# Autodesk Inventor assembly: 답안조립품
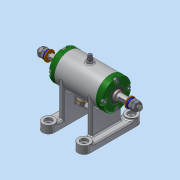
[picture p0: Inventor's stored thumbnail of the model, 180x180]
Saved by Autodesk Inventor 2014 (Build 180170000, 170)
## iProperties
Created: 2015-11
Part Number: 답안조립품
Document SubType Name: Assembly
Designer: 103-21
Author: 103-21
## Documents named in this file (16)
- C:\Users\103-21\Desktop\451110V1030\답안조립품.iam
- C:\Users\103-21\Desktop\451110V1030\1-본체.ipt
- C:\Users\103-21\Desktop\451110V1030\V벨트풀리.ipt
- C:\Users\103-21\Desktop\451110V1030\너트 M 8.ipt
- C:\Users\103-21\Desktop\451110V1030\니플 M 6 x 0.75.ipt
- C:\Users\103-21\Desktop\451110V1030\베어링 15 x 32 x 9.ipt
- C:\Users\103-21\Desktop\451110V1030\볼트 M 6 x 8.ipt
- C:\Users\103-21\Desktop\451110V1030\볼트 M4 x 12.ipt
- C:\Users\103-21\Desktop\451110V1030\스퍼기어.ipt
- C:\Users\103-21\Desktop\451110V1030\스프링와셔 8.ipt
- C:\Users\103-21\Desktop\451110V1030\오일 실 15 25 7.ipt
- C:\Users\103-21\Desktop\451110V1030\와셔 6x11.5.ipt
- C:\Users\103-21\Desktop\451110V1030\와셔 8x17.ipt
- C:\Users\103-21\Desktop\451110V1030\축.ipt
- C:\Users\103-21\Desktop\451110V1030\커버.ipt
- C:\Users\103-21\Desktop\451110V1030\키 3 x 3 x 12.ipt
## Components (12 placed, 4 different names)
1. 1-본체:1
2. V벨트풀리:1 — 각도:3
3. KS B 2023 6002 - 15 x 32 x 9:1
4. KS B 2023 6002 - 15 x 32 x 9:3
5. ISO 4762 M4 x 12:1
6. ISO 4762 M4 x 12:3
7. ISO 4762 M4 x 12:4
8. ISO 4762 M4 x 12:5
9. ISO 4762 M4 x 12:2
10. ISO 4762 M4 x 12:6
11. ISO 4762 M4 x 12:7
12. ISO 4762 M4 x 12:8
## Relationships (1: Angle 1)
- 각도:3 [Angle]: V벨트풀리:1
## Named parameters: d34_d32 = 0, d35_d33 = 0
